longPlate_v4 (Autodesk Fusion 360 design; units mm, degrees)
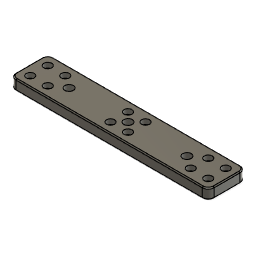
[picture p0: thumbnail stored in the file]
sketch "Sketch1" plane through (0, 0, 0) normal (0, 1, 0) x axis (1, 0, 0)
  line L1 (100, 19) -> (-100, 19)
  line L2 (100, -19) -> (100, 19)
  line L3 (-100, -19) -> (100, -19)
  line L4 (-100, 19) -> (-100, -19)
  line L5 (100, -19) -> (-100, 19)
  line L6 (-100, -19) -> (100, 19)
  point P6 (0, 0)
  point P1 (0, 0)
  point P4 (100, -19)
  point P5 (-100, -19)
  point P3 (100, 19)
  horizontal L1
  perpendicular L1 L2
  parallel L1 L3
  parallel L2 L4
  coincident L5 P6
  coincident L6 P6
  coincident P1 P6
  dimension "d1" distance P4 P5 = 200
  dimension "d2" distance P3 P4 = 38
extrude "Extrude1" new body sketch "Sketch1" profile of L1 L2 L3 L4 along normal blind 10.5
fillet "Fillet1" radius 6
chamfer "Chamfer1" distance 1
sketch "Sketch2" plane through (0, 10.5, 0) normal (0, 1, 0) x axis (-1, 0, 0)
  line L1 (-94, 18) -> (94, 18)
  line L2 (-99, -13) -> (-99, 13)
  line L3 (94, -18) -> (-94, -18)
  line L4 (99, 13) -> (99, -13)
  arc A1 centre (94, 13) radius 5 clockwise from (94, 18) to (99, 13)
  arc A2 centre (-94, 13) radius 5 clockwise from (-99, 13) to (-94, 18)
  arc A3 centre (-94, -13) radius 5 clockwise from (-94, -18) to (-99, -13)
  arc A4 centre (94, -13) radius 5 clockwise from (99, -13) to (94, -18)
  circle C1 centre (-89.8385, 8.8385) radius 3
  circle C2 centre (-72.1615, 8.8385) radius 3
  circle C3 centre (-72.1615, -8.8385) radius 3
  circle C4 centre (-89.8385, -8.8385) radius 3
  circle C5 centre (72.1615, 8.8385) radius 3
  circle C6 centre (89.8385, 8.8385) radius 3
  circle C7 centre (89.8385, -8.8385) radius 3
  circle C8 centre (72.1615, -8.8385) radius 3
  circle C9 centre (-8.838, -8.8385) radius 3
  circle C10 centre (8.839, -8.8385) radius 3
  circle C11 centre (-8.838, 8.8385) radius 3
  circle C12 centre (8.839, 8.8385) radius 3
  point P14 (-89.8385, 8.8385)
  point P16 (-89.8385, -8.8385)
  point P19 (72.1615, 8.8385)
  point P20 (89.8385, 8.8385)
  point P1 (0, 0)
  point P26 (-8.838, 8.8385)
  point P25 (8.839, 8.8385)
  dimension "d12" diameter C4 = 6
  dimension "d13" distance L1 P14 = 9.1615
  dimension "d14" distance L3 P16 = 9.1615
  dimension "d15" distance L2 P16 = 9.1615
  dimension "d20" diameter C8 = 6
  dimension "d21" distance L1 P19 = 9.1615
  dimension "d22" distance L4 P20 = 9.1615
  dimension "d63" diameter C9 = 6
  dimension "d64" distance P1 P26 = 8.838
  dimension "d65" distance P1 P25 = 8.839
  dimension "d10" R-Pattern1-uDistance = 17.677
  dimension "d11" R-Pattern1-vDistance = 17.677
  dimension "d18" R-Pattern2-uDistance = 17.677
  dimension "d19" R-Pattern2-vDistance = 17.677
  dimension "d61" R-Pattern3-uDistance = 17.677
  dimension "d62" R-Pattern3-vDistance = 17.677
extrude "Extrude2" cut sketch "Sketch2" profile of C1 C2 C3 C4 C5 C6 C7 C8 to an object
sketch "Sketch3" plane through (0, 10.5, 0) normal (0, 1, 0) x axis (-1, 0, 0)
  line L1 (-94, 18) -> (94, 18)
  line L2 (-99, -13) -> (-99, 13)
  line L3 (94, -18) -> (-94, -18)
  line L4 (99, 13) -> (99, -13)
  line L5 (-67.5, -17.5) -> (67.5, -17.5)
  line L6 (-67.5, 17.5) -> (-67.5, -17.5)
  line L7 (67.5, 17.5) -> (-67.5, 17.5)
  line L8 (67.5, -17.5) -> (67.5, 17.5)
  line L9 (-67.5, 17.5) -> (67.5, -17.5)
  line L10 (67.5, 17.5) -> (-67.5, -17.5)
  circle C1 centre (-72.1615, 8.8385) radius 3
  circle C2 centre (89.8385, -8.8385) radius 3
  circle C3 centre (72.1615, -8.8385) radius 3
  circle C4 centre (-89.8385, 8.8385) radius 3
  circle C5 centre (-72.1615, -8.8385) radius 3
  circle C6 centre (89.8385, 8.8385) radius 3
  circle C7 centre (72.1615, 8.8385) radius 3
  circle C8 centre (-89.8385, -8.8385) radius 3
  arc A1 centre (94, 13) radius 5 clockwise from (94, 18) to (99, 13)
  arc A2 centre (-94, 13) radius 5 clockwise from (-99, 13) to (-94, 18)
  arc A3 centre (-94, -13) radius 5 clockwise from (-94, -18) to (-99, -13)
  arc A4 centre (94, -13) radius 5 clockwise from (99, -13) to (94, -18)
  circle C9 centre (-59.5, 0) radius 4.3
  circle C10 centre (-59.5, 0) radius 1.225
  circle C11 centre (59.5, 0) radius 1.225
  circle C12 centre (59.5, 0) radius 4.3
  circle C13 centre (0, 0) radius 4.3
  circle C14 centre (0, 0) radius 1.225
  point P26 (0, 0)
  point P1 (0, 0)
  point P24 (-67.5, 17.5)
  point P25 (67.5, 17.5)
  point P23 (-67.5, -17.5)
  point P28 (-59.5, 0)
  point P29 (59.5, 0)
  horizontal L5
  perpendicular L5 L6
  parallel L5 L7
  parallel L6 L8
  coincident L9 P26
  coincident L10 P26
  coincident P1 P26
  dimension "d25" distance P24 P25 = 135
  dimension "d26" distance P23 P24 = 35
  dimension "d28" diameter C10 = 2.45
  dimension "d31" diameter C11 = 2.45
  dimension "d34" distance P1 P28 = 59.5
  dimension "d35" distance P26 P29 = 59.5
  dimension "d52" diameter C14 = 2.45
  dimension "d75" diameter C9 = 8.6
  dimension "d76" diameter C13 = 8.6
  dimension "d77" diameter C12 = 8.6
extrude "Extrude3" cut sketch "Sketch3" profile of C9 C10 C11 C12 against normal blind 7.7
extrude "Extrude4" cut of existing geometry to an object
sketch "Sketch4" plane through (0, 10.5, 0) normal (0, 1, 0) x axis (-1, 0, 0)
  line L1 (-94, 18) -> (94, 18)
  line L2 (-99, -13) -> (-99, 13)
  line L3 (94, -18) -> (-94, -18)
  line L4 (99, 13) -> (99, -13)
  circle C1 centre (59.5, 0) radius 4.3
  circle C2 centre (-59.5, 0) radius 4.3
  circle C3 centre (-72.1615, 8.8385) radius 3
  circle C4 centre (89.8385, -8.8385) radius 3
  circle C5 centre (72.1615, -8.8385) radius 3
  circle C6 centre (-89.8385, 8.8385) radius 3
  circle C7 centre (-72.1615, -8.8385) radius 3
  circle C8 centre (89.8385, 8.8385) radius 3
  circle C9 centre (72.1615, 8.8385) radius 3
  circle C10 centre (-89.8385, -8.8385) radius 3
  arc A1 centre (94, 13) radius 5 clockwise from (94, 18) to (99, 13)
  arc A2 centre (-94, 13) radius 5 clockwise from (-99, 13) to (-94, 18)
  arc A3 centre (-94, -13) radius 5 clockwise from (-94, -18) to (-99, -13)
  arc A4 centre (94, -13) radius 5 clockwise from (99, -13) to (94, -18)
  circle C11 centre (-89.8385, 8.8385) radius 4
  circle C12 centre (-72.1615, 8.8385) radius 4
  circle C13 centre (-89.8385, -8.8385) radius 4
  circle C14 centre (-72.1615, -8.8385) radius 4
  circle C15 centre (72.1615, 8.8385) radius 4
  circle C16 centre (72.1615, 8.8385) radius 3
  circle C17 centre (89.8385, 8.8385) radius 4
  circle C18 centre (72.1615, -8.8385) radius 4
  circle C19 centre (89.8385, -8.8385) radius 4
  circle C20 centre (8.839, 8.8385) radius 4
  circle C21 centre (-8.838, -8.8385) radius 4
  circle C22 centre (8.839, -8.8385) radius 4
  circle C23 centre (-8.838, 8.8385) radius 4
  circle C24 centre (-8.838, 8.8385) radius 3
  concentric C6 C11
  concentric C15 C16
  concentric C23 C24
  dimension "d40" diameter C11 = 8
  dimension "d45" diameter C15 = 8
  dimension "d72" diameter C23 = 8
  dimension "d43" R-Pattern1-uDistance = 17.677
  dimension "d44" R-Pattern1-vDistance = -17.677
  dimension "d48" R-Pattern2-uDistance = 17.677
  dimension "d49" R-Pattern2-vDistance = -17.677
  dimension "d70" R-Pattern3-uDistance = 17.677
  dimension "d71" R-Pattern3-vDistance = -17.677
extrude "Extrude5" cut sketch "Sketch4" profile of C3 C4 C5 C6 C7 C8 C9 C10 C11 C12 C13 C14 C15 C16 C17 C18 C19 against normal blind 5
extrude "Extrude6" cut sketch "Sketch3" profile of C13 C14 against normal blind 7.7
extrude "Extrude7" cut sketch "Sketch3" profile of C14 to an object
extrude "Extrude8" cut sketch "Sketch2" profile of C9 C10 C11 C12 to an object
extrude "Extrude9" cut sketch "Sketch4" profile of C20 C21 C22 C23 C24 against normal blind 5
